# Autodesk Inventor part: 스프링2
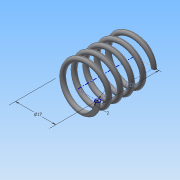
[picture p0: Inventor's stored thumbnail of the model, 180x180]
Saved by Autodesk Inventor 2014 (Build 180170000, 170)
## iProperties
Created: 2016-01
Part Number: 스프링2
Material: 강철, 탄소
Document SubType Name: Modeling
Designer: Administrator
Density: 7.87 g/cm^3
Appearance: 반연마
Mass: 6.44239 g
Surface Area: 16.6857 cm^2
Volume: 0.818602 cm^3
Author: Administrator
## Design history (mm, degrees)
sketch "스케치1"
  geometry: L1 (0, 0)-(8.5, 0); L2 (8.5, 0)-(8.5, 17.5); L3 (8.5, 17.5)-(0, 17.5); L4 (0, 17.5)-(0, 0); C1 r 1 at (8.5, 0)
  constraints: 8 end point, 2 parallel, 1 centre point, 1 coincident, 1 horizontal, 1 perpendicular
  dimensions: "d0" = 17 diameter of L2 L4; "d1" = 17.5 distance of L1.end L2.end (derived); "d2" = 2 diameter of C1
feature "코일1" sketch "스케치1" pitch "d3" = 10; turns "d5" = 5; dims "d4" = 17.5 (= d1), "d6" = 0, angle "d7" = 90 deg, angle "d8" = 90 deg, "d9" = 0, "d10" = 0
node "작업 평면1"
sketch "스케치2"
  geometry: L1 (-9.5, 0)-(-7.5, 0) reference; 1 further point
  constraints: 1 horizontal alignment
extrude "돌출1" cut sketch "스케치2" distance "d12" = 10; taper "d13" = 0 deg
node "작업 평면2"
sketch "스케치3"
  geometry: L1 (-7.5, 0)-(-9.5, 0) reference; 1 further point
  constraints: 1 horizontal alignment
extrude "돌출2" cut sketch "스케치3" distance "d15" = 10; taper "d16" = 0 deg
node "솔리드1"
node "절단 모서리 투영1"
node "절단 모서리 투영2"
other parameters: "d11" = 0, "d14" = 17.5 (= d1)
